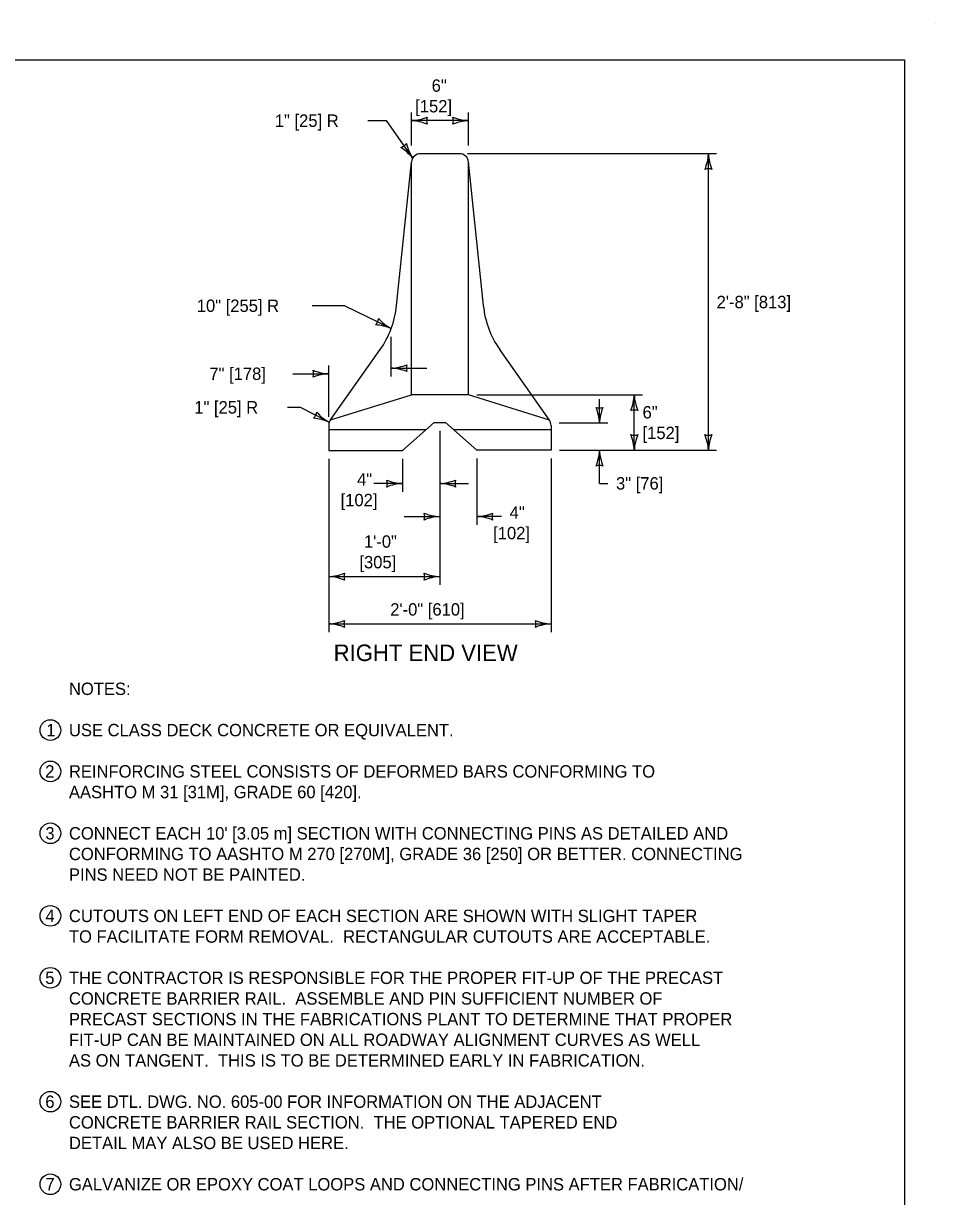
# Model space of a CAD drawing. Extents: x 49991.4 to 50021, y 49987.6 to 50011.4.
# Drawn here: x 50012.48 to 50016.9, y 49993.49 to 49999.18 of the extents above; entities that cross this region are included whole.
import ezdxf

# ---------------------------------------------------------------- set-up
doc = ezdxf.new("R2010")
doc.units = 0
for name, color, linetype in [('Level 1', 7, 'Continuous'), ('Level 2', 7, 'Continuous'), ('Level 3', 7, 'Continuous'), ('Level 4', 7, 'Continuous')]:
    doc.layers.add(name, color=color, linetype=linetype)

msp = doc.modelspace()

# ---------------------------------------------------------------- linework, layer by layer
at = {"layer": 'Level 1'}
for p, q in [((50016.9001, 49999.1756), (50016.9001, 49999.1756)), ((50014.5932, 49998.5447), (50014.4053, 49998.5447)), ((50014.2892, 49997.8091), (50014.3606, 49998.5044)), ((50014.3608, 49997.3771), (50014.3606, 49998.5044)), ((50014.7092, 49997.8086), (50014.6378, 49998.5052)), ((50014.6378, 49997.3771), (50014.6378, 49998.5052)), ((50013.9685, 49997.2561), (50014.2089, 49997.5954)), ((50015.0293, 49997.254), (50014.7888, 49997.5956)), ((50013.9685, 49997.2561), (50014.3608, 49997.3771)), ((50014.6378, 49997.3771), (50014.3608, 49997.3771)), ((50015.0293, 49997.254), (50014.6378, 49997.3771)), ((50013.9603, 49997.2302), (50013.9604, 49997.1068)), ((50014.3176, 49997.1068), (50014.4706, 49997.2424)), ((50014.4706, 49997.2424), (50014.5266, 49997.2424)), ((50014.5266, 49997.2424), (50014.6782, 49997.1077)), ((50015.0374, 49997.2282), (50015.0375, 49997.1077)), ((50013.9604, 49997.1068), (50014.3176, 49997.1068)), ((50015.0375, 49997.1077), (50014.6782, 49997.1077))]:
    msp.add_line(p, q, dxfattribs=at)
msp.add_lwpolyline([(49999.3835, 49998.9992), (50016.7501, 49998.9992), (50016.7501, 49987.7988), (49999.3835, 49987.7988)], close=True, dxfattribs=at)
for centre, radius, start, end in [((50014.4053, 49998.4998), 0.0449, 90, 174.1448), ((50014.5932, 49998.4998), 0.0449, 6.8796, 90), ((50013.8424, 49997.855), 0.4491, 324.6843, 354.1391), ((50015.1559, 49997.8543), 0.4491, 185.8289, 215.1652), ((50014.0052, 49997.2302), 0.0449, 144.7058, 180), ((50014.9925, 49997.2282), 0.0449, 0, 35.0881)]:
    msp.add_arc(centre, radius, start, end, dxfattribs=at)
at = {"layer": 'Level 2'}
for centre in [(50012.6115, 49995.7524), (50012.6115, 49995.5524), (50012.6115, 49995.2524), (50012.6115, 49994.8524), (50012.6115, 49994.5524), (50012.6115, 49993.9524), (50012.6115, 49993.5524)]:
    msp.add_ellipse(centre, major_axis=(0.05, 0), ratio=0.9994, dxfattribs=at)
at = {"layer": 'Level 3'}
for p, q in [((50014.1501, 49998.7047), (50014.2384, 49998.7047)), ((50014.2383, 49998.7047), (50014.3667, 49998.5229)), ((50014.3606, 49998.5847), (50014.3606, 49998.7447)), ((50014.6378, 49998.7047), (50014.3606, 49998.7047)), ((50014.6378, 49998.5847), (50014.6378, 49998.7447)), ((50015.8396, 49998.5447), (50014.6332, 49998.5447)), ((50015.7996, 49997.1077), (50015.7996, 49998.5447)), ((50014.0364, 49997.8082), (50013.8798, 49997.8082)), ((50014.2628, 49997.6971), (50014.0364, 49997.8082)), ((50014.2628, 49997.4656), (50014.2628, 49997.6571)), ((50013.9603, 49997.2701), (50013.9603, 49997.5187)), ((50014.2628, 49997.5056), (50014.4362, 49997.5056)), ((50013.7869, 49997.4787), (50013.9603, 49997.4787)), ((50014.6778, 49997.3763), (50015.4806, 49997.3763)), ((50015.272, 49997.2396), (50015.272, 49997.3563)), ((50015.4406, 49997.1077), (50015.4406, 49997.3763)), ((50013.7598, 49997.316), (50013.8198, 49997.316)), ((50013.9623, 49997.2434), (50013.8198, 49997.316)), ((50015.312, 49997.2396), (50015.076, 49997.2396)), ((50014.4986, 49997.2024), (50014.4986, 49996.4559)), ((50015.0775, 49997.1077), (50015.8396, 49997.1077)), ((50015.272, 49996.9477), (50015.272, 49997.1077)), ((50013.9604, 49997.0668), (50013.9604, 49996.227)), ((50014.3176, 49997.0668), (50014.3176, 49996.9068)), ((50014.6781, 49997.0677), (50014.6781, 49996.7469)), ((50015.0373, 49997.0677), (50015.0373, 49996.227)), ((50014.3176, 49996.9468), (50014.178, 49996.9468)), ((50014.4986, 49996.9468), (50014.6381, 49996.9468)), ((50015.272, 49996.9477), (50015.312, 49996.9477)), ((50014.3252, 49996.7869), (50014.4986, 49996.7869)), ((50014.7967, 49996.7869), (50014.6781, 49996.7869)), ((50013.9604, 49996.4959), (50014.4986, 49996.4959)), ((50013.9604, 49996.267), (50015.0373, 49996.267))]:
    msp.add_line(p, q, dxfattribs=at)
for centre, radius, start, end in [((50014.3491, 49998.9374), 0.233, 272.8273, 292.0772), ((50014.3514, 49998.4826), 0.2223, 67.456, 87.6395), ((50014.4888, 49998.7047), 0.0548, 162.1388, 197.8612), ((50014.6469, 49998.9268), 0.2223, 247.456, 267.6395), ((50014.5096, 49998.7047), 0.0548, 342.1388, 17.8612), ((50014.6493, 49998.472), 0.233, 92.8273, 112.0772), ((50014.2928, 49998.6276), 0.0548, 287.3737, 323.0961), ((50014.5535, 49998.6436), 0.2223, 192.6909, 212.8744), ((50014.1833, 49998.3792), 0.233, 38.0622, 57.312), ((50015.5775, 49998.5539), 0.2223, 337.456, 357.6395), ((50016.0323, 49998.5562), 0.233, 182.8273, 202.0772), ((50015.7996, 49998.4165), 0.0548, 72.1388, 107.8612), ((50014.1477, 49997.7536), 0.0548, 316.0001, 351.7225), ((50014.3689, 49997.8925), 0.2223, 221.3173, 241.5008), ((50014.1706, 49997.4831), 0.233, 66.6886, 85.9385), ((50014.2513, 49997.7383), 0.233, 272.8273, 292.0772), ((50014.2537, 49997.2835), 0.2223, 67.456, 87.6395), ((50014.391, 49997.5056), 0.0548, 162.1388, 197.8612), ((50013.9695, 49997.7008), 0.2223, 247.456, 267.6395), ((50013.8321, 49997.4787), 0.0548, 342.1388, 17.8612), ((50013.9718, 49997.246), 0.233, 92.8273, 112.0772), ((50015.2184, 49997.3855), 0.2223, 337.456, 357.6395), ((50015.6733, 49997.3878), 0.233, 182.8273, 202.0772), ((50013.848, 49997.3016), 0.0548, 315.1418, 350.8641), ((50014.0713, 49997.4372), 0.2223, 220.459, 240.6425), ((50015.272, 49997.3678), 0.0548, 252.1388, 287.8612), ((50015.0393, 49997.2281), 0.233, 2.8273, 22.0772), ((50015.4941, 49997.2304), 0.2223, 157.456, 177.6395), ((50015.4406, 49997.2481), 0.0548, 72.1388, 107.8612), ((50013.8669, 49997.0308), 0.233, 65.8303, 85.0801), ((50015.4406, 49997.2359), 0.0548, 252.1388, 287.8612), ((50015.2079, 49997.0962), 0.233, 2.8273, 22.0772), ((50015.6627, 49997.0985), 0.2223, 157.456, 177.6395), ((50015.7996, 49997.2359), 0.0548, 252.1388, 287.8612), ((50015.5669, 49997.0962), 0.233, 2.8273, 22.0772), ((50016.0218, 49997.0985), 0.2223, 157.456, 177.6395), ((50015.0498, 49997.1169), 0.2223, 337.456, 357.6395), ((50015.5047, 49997.1192), 0.233, 182.8273, 202.0772), ((50015.272, 49996.9795), 0.0548, 72.1388, 107.8612), ((50014.3267, 49997.1689), 0.2223, 247.456, 267.6395), ((50014.1894, 49996.9468), 0.0548, 342.1388, 17.8612), ((50014.3291, 49996.7141), 0.233, 92.8273, 112.0772), ((50014.4871, 49997.1795), 0.233, 272.8273, 292.0772), ((50014.4894, 49996.7247), 0.2223, 67.456, 87.6395), ((50014.6268, 49996.9468), 0.0548, 162.1388, 197.8612), ((50014.5077, 49997.009), 0.2223, 247.456, 267.6395), ((50014.3704, 49996.7869), 0.0548, 342.1388, 17.8612), ((50014.5101, 49996.5542), 0.233, 92.8273, 112.0772), ((50014.6666, 49997.0196), 0.233, 272.8273, 292.0772), ((50014.6689, 49996.5648), 0.2223, 67.456, 87.6395), ((50014.8063, 49996.7869), 0.0548, 162.1388, 197.8612), ((50013.9489, 49996.7286), 0.233, 272.8273, 292.0772), ((50013.9512, 49996.2738), 0.2223, 67.456, 87.6395), ((50014.0886, 49996.4959), 0.0548, 162.1388, 197.8612), ((50014.5077, 49996.7181), 0.2223, 247.456, 267.6395), ((50014.3704, 49996.4959), 0.0548, 342.1388, 17.8612), ((50014.5101, 49996.2632), 0.233, 92.8273, 112.0772), ((50013.9489, 49996.4997), 0.233, 272.8273, 292.0772), ((50013.9512, 49996.0449), 0.2223, 67.456, 87.6395), ((50014.0886, 49996.267), 0.0548, 162.1388, 197.8612), ((50015.0464, 49996.4891), 0.2223, 247.456, 267.6395), ((50014.9091, 49996.267), 0.0548, 342.1388, 17.8612), ((50015.0488, 49996.0343), 0.233, 92.8273, 112.0772)]:
    msp.add_arc(centre, radius, start, end, dxfattribs=at)
at = {"layer": 'Level 4'}
for p, q in [((50013.9603, 49997.2086), (50014.4324, 49997.2086)), ((50014.5646, 49997.2086), (50015.0374, 49997.2086))]:
    msp.add_line(p, q, dxfattribs=at)

# ---------------------------------------------------------------- texts
at = {"layer": 'Level 2'}
for s, height, p in [('6"', 0.06, (50014.4588, 49998.8447)), ('[152]', 0.06, (50014.379, 49998.7447)), ('1" [25] R', 0.06, (50013.699, 49998.6747)), ('10" [255] R', 0.06, (50013.3209, 49997.7782)), ('2\'-8" [813]', 0.06, (50015.8396, 49997.7962)), ('7" [178]', 0.06, (50013.3819, 49997.4487)), ('1" [25] R', 0.06, (50013.3087, 49997.286)), ('6"', 0.06, (50015.4806, 49997.262)), ('[152]', 0.06, (50015.4806, 49997.162)), ('4"', 0.06, (50014.0976, 49996.9368)), ('3" [76]', 0.06, (50015.352, 49996.9177)), ('[102]', 0.06, (50014.0178, 49996.8368)), ('4"', 0.06, (50014.8367, 49996.7769)), ('[102]', 0.06, (50014.7568, 49996.6769)), ('1\'-0"', 0.06, (50014.1307, 49996.6359)), ('[305]', 0.06, (50014.1089, 49996.5359)), ('2\'-0" [610]', 0.06, (50014.2582, 49996.307)), ('RIGHT END VIEW', 0.08, (50013.9841, 49996.087)), ('NOTES:', 0.06, (50012.7015, 49995.9224)), ('1', 0.06, (50012.5917, 49995.7224)), ('USE CLASS DECK CONCRETE OR EQUIVALENT.', 0.06, (50012.7015, 49995.7224)), ('2', 0.06, (50012.5863, 49995.5224)), ('REINFORCING STEEL CONSISTS OF DEFORMED BARS CONFORMING TO', 0.06, (50012.7015, 49995.5224)), ('AASHTO M 31 [31M], GRADE 60 [420].  ', 0.06, (50012.7015, 49995.4224)), ('3', 0.06, (50012.5872, 49995.2227)), ("CONNECT EACH 10' [3.05 m] SECTION WITH CONNECTING PINS AS DETAILED AND", 0.06, (50012.7015, 49995.2224)), ('CONFORMING TO AASHTO M 270 [270M], GRADE 36 [250] OR BETTER. CONNECTING ', 0.06, (50012.7015, 49995.1224)), ('PINS NEED NOT BE PAINTED.', 0.06, (50012.7015, 49995.0224)), ('4', 0.06, (50012.5875, 49994.8224)), ('CUTOUTS ON LEFT END OF EACH SECTION ARE SHOWN WITH SLIGHT TAPER ', 0.06, (50012.7015, 49994.8224)), ('TO FACILITATE FORM REMOVAL.  RECTANGULAR CUTOUTS ARE ACCEPTABLE.', 0.06, (50012.7015, 49994.7224)), ('5', 0.06, (50012.5866, 49994.5224)), ('THE CONTRACTOR IS RESPONSIBLE FOR THE PROPER FIT-UP OF THE PRECAST', 0.06, (50012.7015, 49994.5224)), ('CONCRETE BARRIER RAIL.  ASSEMBLE AND PIN SUFFICIENT NUMBER OF ', 0.06, (50012.7015, 49994.4224)), ('PRECAST SECTIONS IN THE FABRICATIONS PLANT TO DETERMINE THAT PROPER ', 0.06, (50012.7015, 49994.3224)), ('FIT-UP CAN BE MAINTAINED ON ALL ROADWAY ALIGNMENT CURVES AS WELL ', 0.06, (50012.7015, 49994.2224)), ('AS ON TANGENT.  THIS IS TO BE DETERMINED EARLY IN FABRICATION.', 0.06, (50012.7015, 49994.1224)), ('6', 0.06, (50012.5869, 49993.9224)), ('SEE DTL. DWG. NO. 605-00 FOR INFORMATION ON THE ADJACENT', 0.06, (50012.7015, 49993.9224)), ('CONCRETE BARRIER RAIL SECTION.  THE OPTIONAL TAPERED END', 0.06, (50012.7015, 49993.8224)), ('DETAIL MAY ALSO BE USED HERE.', 0.06, (50012.7015, 49993.7224)), ('7', 0.06, (50012.5877, 49993.5224)), ('GALVANIZE OR EPOXY COAT LOOPS AND CONNECTING PINS AFTER FABRICATION/', 0.06, (50012.7015, 49993.5224))]:
    msp.add_text(s, height=height, dxfattribs=at).set_placement(p)

doc.saveas('drawing.dxf')
